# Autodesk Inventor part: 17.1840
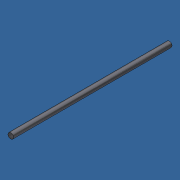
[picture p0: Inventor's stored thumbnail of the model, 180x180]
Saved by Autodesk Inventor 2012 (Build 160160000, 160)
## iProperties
Created: 2007-07
Part Number: 17.1840
Material: Steel
Document SubType Name: Modeling
Designer: Andy Moles
Mass: 90.7543 g
Surface Area: 58.8106 cm^2
Volume: 11.5611 cm^3
Density: 7.85 g/cm^3
Description: CUT TO  L - 70mm(2.756")
Vendor: F
Stock Number: SHAFT 8
Author: Andy Moles
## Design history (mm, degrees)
sketch "Sketch1"
  geometry: C1 r 4 at (0, 0); 1 further point
  constraints: 1 centre point, 1 coincident
  dimensions: "d0" = 8 diameter of C1
extrude "Extrusion1" new body sketch "Sketch1" stored distance "d1" = 230 (= ROD_LENGTH); taper "d2" = 0 deg
body "Solid1"
other parameters: "PVC_TUBE_LENGTH" = 207 (computed from BELT_WIDTH_L) [user parameter; used in 1 equation term], "ROD_LENGTH" = 230 (computed from PVC_TUBE_LENGTH) [user parameter; used in 1 equation term]
